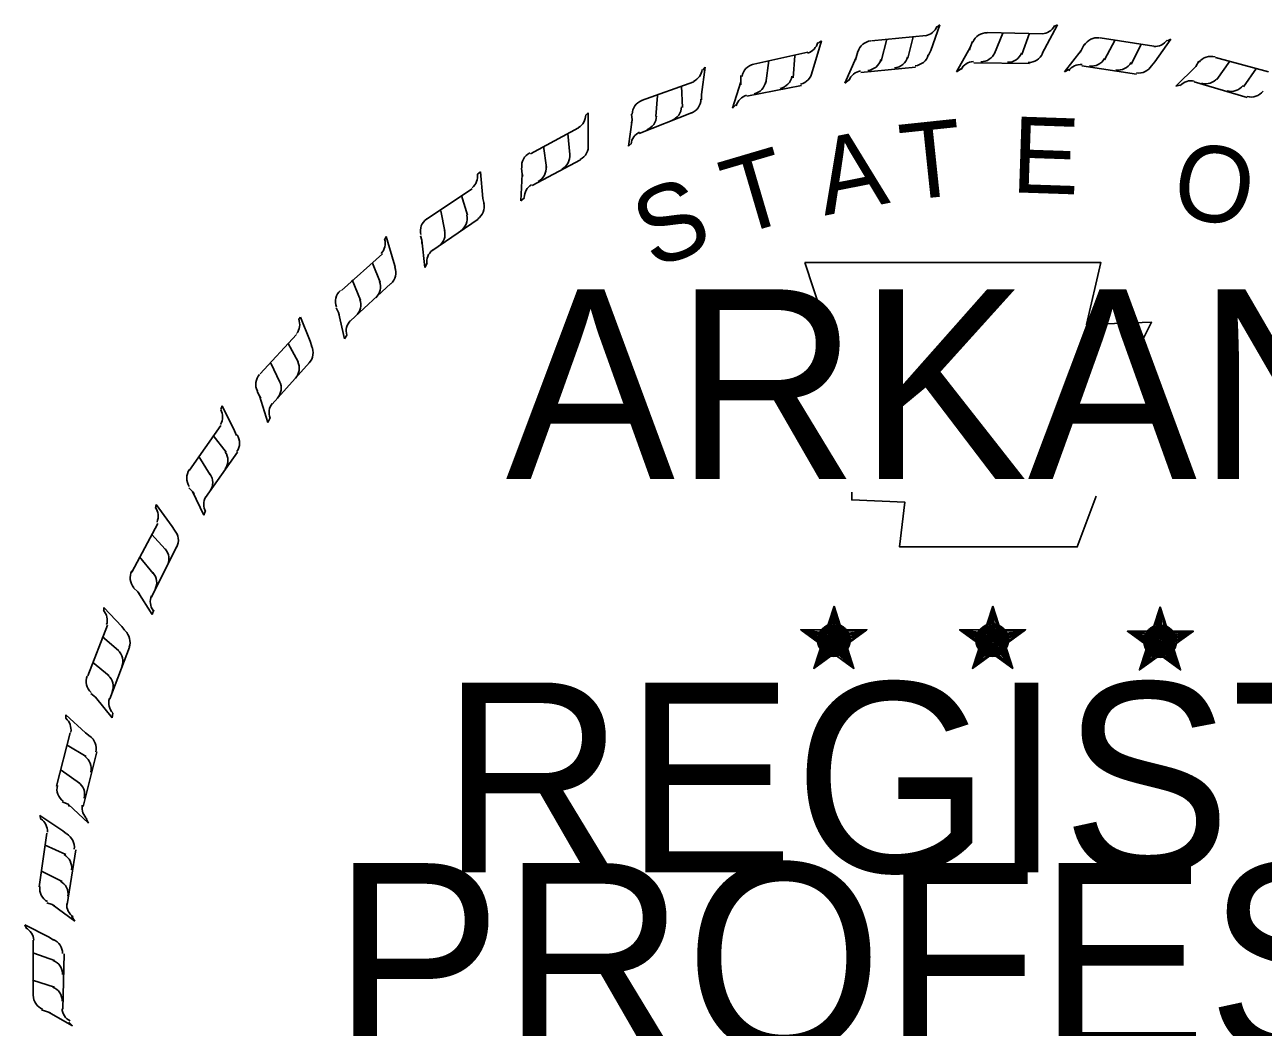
# Model space of a CAD drawing. Extents: x 117751.5 to 117785.6, y 28052.1 to 28074.
# Drawn here: x 117776.184 to 117777.407, y 28054.465 to 28055.456 of the extents above; entities that cross this region are included whole.
import ezdxf

# ---------------------------------------------------------------- set-up
doc = ezdxf.new("R2010")
doc.units = 0
doc.layers.add('Stamp-ChrisC', color=7, linetype='Continuous')

msp = doc.modelspace()

# ---------------------------------------------------------------- linework, layer by layer
at = {"layer": 'Stamp-ChrisC'}
for p, q in [((117777.0784, 28055.4301), (117777.0874, 28055.4556)), ((117777.0874, 28055.4556), (117777.0844, 28055.4533)), ((117777.1909, 28055.4316), (117777.2036, 28055.4556)), ((117777.2036, 28055.4556), (117777.2006, 28055.4541)), ((117776.9629, 28055.4143), (117776.9704, 28055.4398)), ((117776.9704, 28055.4398), (117776.9674, 28055.4376)), ((117777.0199, 28055.4398), (117777.0739, 28055.4451)), ((117777.0296, 28055.4196), (117777.0349, 28055.4413)), ((117777.0559, 28055.4226), (117777.0611, 28055.4436)), ((117777.1196, 28055.4391), (117777.1174, 28055.4331)), ((117777.1346, 28055.4481), (117777.1886, 28055.4466)), ((117777.1414, 28055.4271), (117777.1496, 28055.4473)), ((117777.1684, 28055.4263), (117777.1759, 28055.4473)), ((117777.2456, 28055.4428), (117777.2989, 28055.4346)), ((117777.2501, 28055.4211), (117777.2606, 28055.4406)), ((117777.2996, 28055.4188), (117777.3154, 28055.4413)), ((117777.3154, 28055.4413), (117777.3124, 28055.4398)), ((117776.9036, 28055.4166), (117776.9569, 28055.4286)), ((117777.0064, 28055.4293), (117777.0049, 28055.4233)), ((117777.0761, 28055.4256), (117777.0784, 28055.4301)), ((117777.1174, 28055.4331), (117777.1039, 28055.4091)), ((117777.1174, 28055.4331), (117777.1166, 28055.4308)), ((117777.1886, 28055.4271), (117777.1909, 28055.4316)), ((117777.2269, 28055.4301), (117777.2104, 28055.4091)), ((117777.2269, 28055.4301), (117777.2261, 28055.4286)), ((117777.2299, 28055.4361), (117777.2269, 28055.4301)), ((117777.2764, 28055.4166), (117777.2861, 28055.4361)), ((117776.8519, 28055.3866), (117776.8556, 28055.4136)), ((117776.8556, 28055.4136), (117776.8534, 28055.4106)), ((117776.9156, 28055.3978), (117776.9186, 28055.4203)), ((117776.9426, 28055.4031), (117776.9441, 28055.4248)), ((117776.9614, 28055.4091), (117776.9629, 28055.4143)), ((117777.0049, 28055.4233), (117776.9936, 28055.3978)), ((117777.0049, 28055.4233), (117777.0041, 28055.4211)), ((117777.0634, 28055.4136), (117777.0094, 28055.4083)), ((117777.1759, 28055.4173), (117777.1211, 28055.4181)), ((117777.2816, 28055.4068), (117777.2276, 28055.4151)), ((117777.2966, 28055.4151), (117777.2996, 28055.4188)), ((117777.3401, 28055.4143), (117777.3206, 28055.3948)), ((117777.3401, 28055.4143), (117777.3386, 28055.4128)), ((117777.3431, 28055.4196), (117777.3401, 28055.4143)), ((117777.3596, 28055.4233), (117777.4121, 28055.4091)), ((117777.3611, 28055.4016), (117777.3739, 28055.4196)), ((117776.8909, 28055.4053), (117776.8909, 28055.3993)), ((117776.9936, 28055.3978), (117776.9981, 28055.4016)), ((117777.1039, 28055.4091), (117777.1084, 28055.4121)), ((117777.2104, 28055.4091), (117777.2149, 28055.4113)), ((117777.3874, 28055.3941), (117777.4001, 28055.4128)), ((117776.7926, 28055.3806), (117776.8444, 28055.3993)), ((117776.8331, 28055.3738), (117776.8324, 28055.3948)), ((117776.8909, 28055.3993), (117776.8826, 28055.3731)), ((117776.8909, 28055.3993), (117776.8909, 28055.3963)), ((117776.9509, 28055.3956), (117776.8969, 28055.3851)), ((117777.3206, 28055.3948), (117777.3259, 28055.3963)), ((117777.3911, 28055.3836), (117777.3386, 28055.3993)), ((117776.8069, 28055.3648), (117776.8084, 28055.3858)), ((117776.8519, 28055.3813), (117776.8519, 28055.3866)), ((117776.8826, 28055.3731), (117776.8864, 28055.3768)), ((117776.7401, 28055.3686), (117776.7379, 28055.3663)), ((117776.7401, 28055.3423), (117776.7401, 28055.3686)), ((117776.7829, 28055.3671), (117776.7836, 28055.3618)), ((117776.8421, 28055.3686), (117776.7904, 28055.3483)), ((117776.6831, 28055.3281), (117776.7304, 28055.3536)), ((117776.7836, 28055.3618), (117776.7799, 28055.3356)), ((117776.7836, 28055.3618), (117776.7829, 28055.3588)), ((117776.7221, 28055.3273), (117776.7199, 28055.3483)), ((117776.7401, 28055.3371), (117776.7401, 28055.3423)), ((117776.6989, 28055.3146), (117776.6959, 28055.3356)), ((117776.7799, 28055.3356), (117776.7829, 28055.3386)), ((117776.7326, 28055.3221), (117776.6846, 28055.2966)), ((117776.6336, 28055.3101), (117776.6306, 28055.3078)), ((117776.6359, 28055.2838), (117776.6336, 28055.3101)), ((117776.6749, 28055.3078), (117776.6734, 28055.2816)), ((117776.6741, 28055.3138), (117776.6749, 28055.3078)), ((117776.6749, 28055.3078), (117776.6756, 28055.3056)), ((117776.5804, 28055.2636), (117776.6254, 28055.2936)), ((117776.6209, 28055.2673), (117776.6149, 28055.2868)), ((117776.6374, 28055.2786), (117776.6359, 28055.2838)), ((117776.6734, 28055.2816), (117776.6771, 28055.2846)), ((117776.5984, 28055.2516), (117776.5946, 28055.2718)), ((117776.6314, 28055.2636), (117776.5856, 28055.2321)), ((117776.5406, 28055.2463), (117776.5391, 28055.2433)), ((117776.5481, 28055.2208), (117776.5406, 28055.2463)), ((117776.5744, 28055.2471), (117776.5759, 28055.2426)), ((117776.5759, 28055.2426), (117776.5789, 28055.2156)), ((117776.5759, 28055.2426), (117776.5759, 28055.2396)), ((117776.4964, 28055.1931), (117776.5369, 28055.2291)), ((117776.5346, 28055.2013), (117776.5271, 28055.2201)), ((117776.5496, 28055.2163), (117776.5481, 28055.2208)), ((117776.5789, 28055.2156), (117776.5811, 28055.2201)), ((117776.5451, 28055.1998), (117776.5054, 28055.1631)), ((117776.5151, 28055.1833), (117776.5069, 28055.2036)), ((117776.4911, 28055.1758), (117776.4934, 28055.1713)), ((117776.4934, 28055.1713), (117776.4994, 28055.1451)), ((117776.4934, 28055.1713), (117776.4941, 28055.1691)), ((117776.4559, 28055.1668), (117776.4544, 28055.1646)), ((117776.4656, 28055.1428), (117776.4559, 28055.1668)), ((117776.4161, 28055.1106), (117776.4521, 28055.1496)), ((117776.4994, 28055.1451), (117776.5016, 28055.1488)), ((117776.4536, 28055.1226), (117776.4439, 28055.1406)), ((117776.4671, 28055.1376), (117776.4656, 28055.1428)), ((117776.4356, 28055.1023), (117776.4266, 28055.1211)), ((117776.4649, 28055.1218), (117776.4281, 28055.0806)), ((117776.4131, 28055.0933), (117776.4154, 28055.0888)), ((117776.4154, 28055.0888), (117776.4236, 28055.0626)), ((117776.4154, 28055.0888), (117776.4169, 28055.0866)), ((117776.3786, 28055.0791), (117776.3771, 28055.0753)), ((117776.3906, 28055.0543), (117776.3786, 28055.0791)), ((117776.3464, 28055.0153), (117776.3771, 28055.0596)), ((117776.4236, 28055.0626), (117776.4259, 28055.0671)), ((117776.3824, 28055.0333), (117776.3696, 28055.0498)), ((117776.3929, 28055.0498), (117776.3906, 28055.0543)), ((117776.3666, 28055.0108), (117776.3554, 28055.0288)), ((117776.3936, 28055.0333), (117776.3621, 28054.9883)), ((117776.3456, 28054.9981), (117776.3494, 28054.9943)), ((117776.3494, 28054.9943), (117776.3606, 28054.9711)), ((117776.3494, 28054.9943), (117776.3509, 28054.9921)), ((117776.3134, 28054.9816), (117776.3126, 28054.9778)), ((117776.3291, 28054.9598), (117776.3134, 28054.9816)), ((117776.3606, 28054.9711), (117776.3621, 28054.9756)), ((117776.2894, 28054.9148), (117776.3149, 28054.9628)), ((117776.3224, 28054.9373), (117776.3089, 28054.9523)), ((117776.3314, 28054.9561), (117776.3291, 28054.9598)), ((117776.3336, 28054.9396), (117776.3089, 28054.8901)), ((117776.3104, 28054.9133), (117776.2969, 28054.9298)), ((117776.2909, 28054.8991), (117776.2954, 28054.8953)), ((117776.2954, 28054.8953), (117776.3096, 28054.8728)), ((117776.2954, 28054.8953), (117776.2969, 28054.8931)), ((117776.2796, 28054.8608), (117776.2616, 28054.8796)), ((117776.2616, 28054.8796), (117776.2616, 28054.8766)), ((117776.3096, 28054.8728), (117776.3111, 28054.8773)), ((117776.9831, 28054.8811), (117776.9779, 28054.8586)), ((117776.9831, 28054.8811), (117776.9794, 28054.8578)), ((117776.9831, 28054.8811), (117776.9816, 28054.8578)), ((117776.9831, 28054.8473), (117776.9831, 28054.8811)), ((117776.9831, 28054.8811), (117776.9891, 28054.8578)), ((117776.9831, 28054.8811), (117776.9876, 28054.8578)), ((117776.9831, 28054.8811), (117776.9854, 28054.8578)), ((117777.1399, 28054.8811), (117777.1339, 28054.8586)), ((117777.1399, 28054.8811), (117777.1361, 28054.8578)), ((117777.1399, 28054.8811), (117777.1376, 28054.8578)), ((117777.1399, 28054.8473), (117777.1399, 28054.8811)), ((117777.1399, 28054.8811), (117777.1459, 28054.8578)), ((117777.1399, 28054.8811), (117777.1444, 28054.8578)), ((117777.1399, 28054.8811), (117777.1414, 28054.8578)), ((117777.3049, 28054.8803), (117777.2996, 28054.8571)), ((117777.3049, 28054.8803), (117777.3011, 28054.8571)), ((117777.3049, 28054.8803), (117777.3034, 28054.8571)), ((117777.3049, 28054.8458), (117777.3049, 28054.8803)), ((117777.3049, 28054.8803), (117777.3116, 28054.8571)), ((117777.3049, 28054.8803), (117777.3101, 28054.8571)), ((117777.3049, 28054.8803), (117777.3071, 28054.8571)), ((117776.2459, 28054.8121), (117776.2654, 28054.8623)), ((117776.2766, 28054.8368), (117776.2601, 28054.8511)), ((117776.2826, 28054.8571), (117776.2796, 28054.8608)), ((117776.9501, 28054.8578), (117776.9831, 28054.8473)), ((117776.9501, 28054.8578), (117776.9741, 28054.8548)), ((117776.9501, 28054.8578), (117776.9741, 28054.8533)), ((117776.9501, 28054.8578), (117776.9734, 28054.8518)), ((117776.9501, 28054.8578), (117776.9726, 28054.8481)), ((117776.9501, 28054.8578), (117776.9726, 28054.8458)), ((117776.9501, 28054.8578), (117776.9726, 28054.8436)), ((117777.0154, 28054.8578), (117776.9831, 28054.8473)), ((117777.0154, 28054.8578), (117776.9869, 28054.8556)), ((117777.0154, 28054.8578), (117776.9891, 28054.8526)), ((117777.0154, 28054.8578), (117776.9891, 28054.8511)), ((117777.0154, 28054.8578), (117776.9951, 28054.8488)), ((117777.0154, 28054.8578), (117776.9966, 28054.8481)), ((117777.0154, 28054.8578), (117776.9981, 28054.8466)), ((117777.1069, 28054.8578), (117777.1399, 28054.8473)), ((117777.1069, 28054.8578), (117777.1309, 28054.8548)), ((117777.1069, 28054.8578), (117777.1301, 28054.8533)), ((117777.1069, 28054.8578), (117777.1301, 28054.8518)), ((117777.1069, 28054.8578), (117777.1294, 28054.8481)), ((117777.1069, 28054.8578), (117777.1286, 28054.8458)), ((117777.1069, 28054.8578), (117777.1286, 28054.8436)), ((117777.1721, 28054.8578), (117777.1399, 28054.8473)), ((117777.1721, 28054.8578), (117777.1436, 28054.8556)), ((117777.1721, 28054.8578), (117777.1451, 28054.8526)), ((117777.1721, 28054.8578), (117777.1451, 28054.8511)), ((117777.1721, 28054.8578), (117777.1511, 28054.8488)), ((117777.1721, 28054.8578), (117777.1526, 28054.8481)), ((117777.1721, 28054.8578), (117777.1541, 28054.8466)), ((117777.2726, 28054.8563), (117777.3049, 28054.8458)), ((117777.2726, 28054.8563), (117777.2966, 28054.8541)), ((117777.2726, 28054.8563), (117777.2966, 28054.8526)), ((117777.2726, 28054.8563), (117777.2951, 28054.8503)), ((117777.2726, 28054.8563), (117777.2951, 28054.8473)), ((117777.2726, 28054.8563), (117777.2944, 28054.8451)), ((117777.2726, 28054.8563), (117777.2944, 28054.8428)), ((117777.3379, 28054.8563), (117777.3049, 28054.8458)), ((117777.3379, 28054.8563), (117777.3086, 28054.8541)), ((117777.3379, 28054.8563), (117777.3109, 28054.8518)), ((117777.3379, 28054.8563), (117777.3109, 28054.8503)), ((117777.3379, 28054.8563), (117777.3169, 28054.8481)), ((117777.3379, 28054.8563), (117777.3184, 28054.8466)), ((117777.3379, 28054.8563), (117777.3199, 28054.8458)), ((117776.2871, 28054.8406), (117776.2676, 28054.7896)), ((117776.9629, 28054.8196), (117776.9831, 28054.8473)), ((117776.9629, 28054.8196), (117776.9734, 28054.8451)), ((117776.9629, 28054.8196), (117776.9749, 28054.8421)), ((117776.9629, 28054.8196), (117776.9764, 28054.8413)), ((117776.9629, 28054.8196), (117776.9831, 28054.8398)), ((117776.9629, 28054.8196), (117776.9794, 28054.8391)), ((117777.0026, 28054.8196), (117776.9831, 28054.8473)), ((117777.0026, 28054.8196), (117776.9831, 28054.8391)), ((117777.0026, 28054.8196), (117776.9861, 28054.8391)), ((117777.0026, 28054.8196), (117776.9891, 28054.8421)), ((117777.0026, 28054.8196), (117776.9899, 28054.8466)), ((117777.0026, 28054.8196), (117776.9921, 28054.8466)), ((117777.1196, 28054.8196), (117777.1399, 28054.8473)), ((117777.1196, 28054.8196), (117777.1301, 28054.8451)), ((117777.1196, 28054.8196), (117777.1309, 28054.8421)), ((117777.1196, 28054.8196), (117777.1331, 28054.8413)), ((117777.1196, 28054.8196), (117777.1391, 28054.8398)), ((117777.1196, 28054.8196), (117777.1361, 28054.8391)), ((117777.1594, 28054.8196), (117777.1391, 28054.8391)), ((117777.1594, 28054.8196), (117777.1399, 28054.8473)), ((117777.1594, 28054.8196), (117777.1429, 28054.8391)), ((117777.1594, 28054.8196), (117777.1459, 28054.8421)), ((117777.1594, 28054.8196), (117777.1466, 28054.8466)), ((117777.1594, 28054.8196), (117777.1489, 28054.8466)), ((117777.2846, 28054.8181), (117777.3049, 28054.8458)), ((117777.2846, 28054.8181), (117777.2951, 28054.8436)), ((117777.2846, 28054.8181), (117777.2966, 28054.8413)), ((117777.2846, 28054.8181), (117777.2989, 28054.8406)), ((117777.2846, 28054.8181), (117777.3049, 28054.8383)), ((117777.3251, 28054.8181), (117777.3049, 28054.8458)), ((117777.3251, 28054.8181), (117777.3049, 28054.8383)), ((117777.3251, 28054.8181), (117777.3116, 28054.8413)), ((117777.3251, 28054.8181), (117777.3124, 28054.8451)), ((117777.3251, 28054.8181), (117777.3146, 28054.8458)), ((117776.9629, 28054.8196), (117776.9831, 28054.8368)), ((117777.0026, 28054.8196), (117776.9831, 28054.8368)), ((117777.1196, 28054.8196), (117777.1399, 28054.8368)), ((117777.1594, 28054.8196), (117777.1391, 28054.8368)), ((117777.2846, 28054.8181), (117777.3011, 28054.8376)), ((117777.2846, 28054.8181), (117777.3056, 28054.8361)), ((117777.3251, 28054.8181), (117777.3049, 28054.8353)), ((117777.3251, 28054.8181), (117777.3086, 28054.8376)), ((117776.2669, 28054.8121), (117776.2504, 28054.8256)), ((117776.2489, 28054.7948), (117776.2534, 28054.7911)), ((117776.2534, 28054.7911), (117776.2699, 28054.7708)), ((117776.2534, 28054.7911), (117776.2549, 28054.7896)), ((117776.2436, 28054.7558), (117776.2241, 28054.7738)), ((117776.2241, 28054.7738), (117776.2241, 28054.7701)), ((117776.2699, 28054.7708), (117776.2706, 28054.7753)), ((117776.2151, 28054.7033), (117776.2286, 28054.7558)), ((117776.2481, 28054.7521), (117776.2436, 28054.7558)), ((117776.2444, 28054.7326), (117776.2256, 28054.7438)), ((117776.2549, 28054.7371), (117776.2414, 28054.6831)), ((117776.2376, 28054.7063), (117776.2196, 28054.7191)), ((117776.2204, 28054.6876), (117776.2264, 28054.6853)), ((117776.2264, 28054.6853), (117776.2466, 28054.6666)), ((117776.2264, 28054.6853), (117776.2279, 28054.6831)), ((117776.2211, 28054.6591), (117776.1986, 28054.6741)), ((117776.1986, 28054.6741), (117776.1994, 28054.6703)), ((117776.2466, 28054.6666), (117776.2444, 28054.6711)), ((117776.1979, 28054.6036), (117776.2054, 28054.6568)), ((117776.2249, 28054.6561), (117776.2211, 28054.6591)), ((117776.2241, 28054.6358), (117776.2039, 28054.6448)), ((117776.2339, 28054.6403), (117776.2256, 28054.5863)), ((117776.2204, 28054.6088), (117776.2001, 28054.6193)), ((117776.2054, 28054.5878), (117776.2106, 28054.5863)), ((117776.2106, 28054.5863), (117776.2331, 28054.5698)), ((117776.2106, 28054.5863), (117776.2129, 28054.5848)), ((117776.2331, 28054.5698), (117776.2301, 28054.5743)), ((117776.2076, 28054.5541), (117776.1836, 28054.5661)), ((117776.1836, 28054.5661), (117776.1851, 28054.5631)), ((117776.1919, 28054.4971), (117776.1919, 28054.5511)), ((117776.2121, 28054.5511), (117776.2076, 28054.5541)), ((117776.2129, 28054.5308), (117776.1926, 28054.5383)), ((117776.2226, 28054.5376), (117776.2211, 28054.4828)), ((117776.2129, 28054.5046), (117776.1911, 28054.5113)), ((117776.2001, 28054.4821), (117776.2069, 28054.4798)), ((117776.2069, 28054.4798), (117776.2309, 28054.4663)), ((117776.2069, 28054.4798), (117776.2091, 28054.4791)), ((117776.2309, 28054.4663), (117776.2271, 28054.4701))]:
    msp.add_line(p, q, dxfattribs=at)
for points in [[(117776.9539, 28055.2208), (117776.9794, 28055.1436)], [(117777.2831, 28055.1346), (117777.2966, 28055.1616), (117777.2321, 28055.1593), (117777.2464, 28055.2208), (117776.9539, 28055.2208)], [(117777.0004, 28054.9936), (117777.0004, 28054.9861), (117777.0529, 28054.9838), (117777.0476, 28054.9396), (117777.2231, 28054.9396), (117777.2419, 28054.9898)], [(117776.9831, 28054.8811), (117777.0026, 28054.8196), (117776.9501, 28054.8578), (117777.0154, 28054.8578), (117776.9629, 28054.8196), (117776.9831, 28054.8811)], [(117777.1399, 28054.8811), (117777.1594, 28054.8196), (117777.1069, 28054.8578), (117777.1721, 28054.8578), (117777.1196, 28054.8196), (117777.1399, 28054.8811)], [(117777.3049, 28054.8803), (117777.3251, 28054.8181), (117777.2726, 28054.8563), (117777.3379, 28054.8563), (117777.2846, 28054.8181), (117777.3049, 28054.8803)]]:
    msp.add_lwpolyline(points, dxfattribs=at)
for centre, radius in [((117776.9828, 28054.8474), 0.0161), ((117777.1392, 28054.8474), 0.0161), ((117777.3049, 28054.8463), 0.0161), ((117776.9828, 28054.8474), 0.0146), ((117776.9828, 28054.8474), 0.0136), ((117776.9828, 28054.8474), 0.0124), ((117776.9828, 28054.8474), 0.0109), ((117776.9828, 28054.8474), 0.0101), ((117776.9828, 28054.8474), 0.00929), ((117776.9828, 28054.8474), 0.008), ((117776.9828, 28054.8474), 0.00701), ((117776.9828, 28054.8474), 0.00583), ((117776.9828, 28054.8474), 0.00464), ((117776.9828, 28054.8474), 0.00346), ((117776.9828, 28054.8474), 0.00278), ((117777.1392, 28054.8474), 0.0146), ((117777.1392, 28054.8474), 0.0136), ((117777.1392, 28054.8474), 0.0124), ((117777.1392, 28054.8474), 0.0109), ((117777.1392, 28054.8474), 0.0101), ((117777.1392, 28054.8474), 0.00929), ((117777.1392, 28054.8474), 0.008), ((117777.1392, 28054.8474), 0.00701), ((117777.1392, 28054.8474), 0.00583), ((117777.1392, 28054.8474), 0.00464), ((117777.1392, 28054.8474), 0.00346), ((117777.1392, 28054.8474), 0.00278), ((117777.3049, 28054.8463), 0.0146), ((117777.3049, 28054.8463), 0.0136), ((117777.3049, 28054.8463), 0.0124), ((117777.3049, 28054.8463), 0.0109), ((117777.3049, 28054.8463), 0.0101), ((117777.3049, 28054.8463), 0.00929), ((117777.3049, 28054.8463), 0.008), ((117777.3049, 28054.8463), 0.00701), ((117777.3049, 28054.8463), 0.00583), ((117777.3049, 28054.8463), 0.00464), ((117776.9828, 28054.8474), 0.00135), ((117777.1392, 28054.8474), 0.00135), ((117777.3049, 28054.8463), 0.00346), ((117777.3049, 28054.8463), 0.00278), ((117777.3049, 28054.8463), 0.00135)]:
    msp.add_circle(centre, radius, dxfattribs=at)
for centre, start, end in [((117777.0708, 28055.4593), 279.9249, 338.7128), ((117777.1875, 28055.4614), 273.4236, 332.2115), ((117776.9526, 28055.4419), 286.2701, 345.0579), ((117777.0207, 28055.4249), 95.6641, 164.0381), ((117777.1338, 28055.4328), 89.1628, 157.5368), ((117777.2428, 28055.4279), 81.4231, 149.797), ((117777.2998, 28055.449), 265.6839, 324.4717), ((117777.0617, 28055.4298), 275.6641, 344.0381), ((117777.1281, 28055.4338), 269.1628, 337.5368), ((117777.1545, 28055.4333), 269.1628, 337.5368), ((117777.175, 28055.433), 269.1628, 337.5368), ((117776.9066, 28055.4021), 102.0093, 170.3833), ((117777.0149, 28055.4252), 275.6641, 344.0381), ((117777.0413, 28055.4277), 275.6641, 344.0381), ((117777.1214, 28055.4045), 93.4236, 152.2115), ((117777.2267, 28055.4016), 85.6839, 144.4717), ((117777.2373, 28055.4296), 261.4231, 329.797), ((117777.2634, 28055.4256), 261.4231, 329.797), ((117777.2837, 28055.4226), 261.4231, 329.797), ((117777.3551, 28055.4096), 73.9909, 142.3649), ((117776.8379, 28055.4131), 294.8371, 353.6249), ((117776.9267, 28055.4072), 282.0093, 350.3833), ((117776.9467, 28055.4115), 282.0093, 350.3833), ((117777.0116, 28055.3954), 99.9249, 158.7128), ((117777.3498, 28055.412), 253.9909, 322.3649), ((117776.9008, 28055.4018), 282.0093, 350.3833), ((117777.3357, 28055.3855), 78.2517, 137.0395), ((117777.3752, 28055.4046), 253.9909, 322.3649), ((117777.395, 28055.399), 253.9909, 322.3649), ((117776.7983, 28055.3669), 110.5763, 178.9503), ((117776.8366, 28055.3822), 290.5763, 358.9503), ((117776.9007, 28055.3718), 106.2701, 165.0579), ((117776.7228, 28055.3665), 301.9545, 0.7423), ((117776.7927, 28055.3657), 290.5763, 358.9503), ((117776.8174, 28055.3749), 290.5763, 358.9503), ((117776.7971, 28055.3361), 114.8371, 173.6249), ((117776.6892, 28055.3158), 117.6937, 186.0677), ((117776.7072, 28055.3261), 297.6937, 6.0677), ((117776.7254, 28055.3357), 297.6937, 6.0677), ((117776.6838, 28055.3139), 297.6937, 6.0677), ((117776.6161, 28055.306), 309.1135, 7.9014), ((117776.6918, 28055.285), 121.9545, 180.7423), ((117776.6225, 28055.2758), 304.8528, 13.2267), ((117776.6057, 28055.264), 304.8528, 13.2267), ((117776.5891, 28055.2516), 124.8528, 193.2267), ((117776.5248, 28055.2397), 316.8235, 15.6113), ((117776.5839, 28055.249), 304.8528, 13.2267), ((117776.5955, 28055.2213), 129.1135, 187.9014), ((117776.5353, 28055.2106), 312.5627, 20.9367), ((117776.5054, 28055.1821), 132.5627, 200.9367), ((117776.5202, 28055.1967), 312.5627, 20.9367), ((117776.5007, 28055.1789), 312.5627, 20.9367), ((117776.4404, 28055.1594), 322.2653, 21.0531), ((117776.5159, 28055.153), 136.8235, 195.6113), ((117776.4536, 28055.1314), 318.0045, 26.3785), ((117776.4399, 28055.1161), 318.0045, 26.3785), ((117776.4266, 28055.1002), 138.0045, 206.3785), ((117776.4221, 28055.0966), 318.0045, 26.3785), ((117776.3642, 28055.0681), 329.9636, 28.7515), ((117776.4397, 28055.0723), 142.2653, 201.0531), ((117776.381, 28055.0421), 325.7028, 34.0768), ((117776.3694, 28055.0251), 325.7028, 34.0768), ((117776.3584, 28055.0076), 145.7028, 214.0768), ((117776.3545, 28055.0033), 325.7028, 34.0768), ((117776.3752, 28054.9816), 149.9636, 208.7515), ((117776.3006, 28054.9699), 337.2243, 36.0121), ((117776.3205, 28054.9463), 332.9635, 41.3375), ((117776.3112, 28054.9279), 332.9635, 41.3375), ((117776.3025, 28054.9091), 152.9635, 221.3375), ((117776.2991, 28054.9044), 332.9635, 41.3375), ((117776.3224, 28054.8855), 157.2243, 216.0121), ((117776.2503, 28054.867), 343.6465, 42.4343), ((117776.2728, 28054.8457), 339.3857, 47.7597), ((117776.2656, 28054.8265), 339.3857, 47.7597), ((117776.259, 28054.8068), 159.3857, 227.7597), ((117776.2562, 28054.8017), 339.3857, 47.7597), ((117776.2814, 28054.7855), 163.6465, 222.4343), ((117776.2145, 28054.759), 350.445, 49.2329), ((117776.2393, 28054.7405), 346.1842, 54.5582), ((117776.2344, 28054.7206), 346.1842, 54.5582), ((117776.2302, 28054.7003), 166.1842, 234.5582), ((117776.228, 28054.6949), 346.1842, 54.5582), ((117776.255, 28054.6818), 170.445, 229.2329), ((117776.1912, 28054.6587), 356.646, 55.4338), ((117776.2178, 28054.643), 352.3852, 60.7592), ((117776.2152, 28054.6226), 352.3852, 60.7592), ((117776.2116, 28054.5964), 352.3852, 60.7592), ((117776.2132, 28054.602), 172.3852, 240.7592), ((117776.2398, 28054.5863), 176.646, 235.4338), ((117776.1778, 28054.5499), 3.9474, 62.7352), ((117776.2062, 28054.5378), 359.6866, 68.0606), ((117776.2062, 28054.5172), 359.6866, 68.0606), ((117776.2068, 28054.4965), 179.6866, 248.0606), ((117776.2059, 28054.4908), 359.6866, 68.0606), ((117776.2352, 28054.4843), 183.9474, 242.7352)]:
    msp.add_arc(centre, 0.0148, start, end, dxfattribs=at)

# ---------------------------------------------------------------- texts
for s, rotation, p in [('E', 358.0732, (117777.1574, 28055.2901)), ('T', 6.0228, (117777.0524, 28055.2819)), ('A', 11.2132, (117776.9736, 28055.2669)), ('T', 16.4036, (117776.8866, 28055.2466)), ('O', 350.4515, (117777.3141, 28055.2676)), ('S', 21.594, (117776.8041, 28055.2136))]:
    msp.add_text(s, height=0.075, rotation=rotation, dxfattribs=at).set_placement(p)
for s, height, p in [('ARKANSAS', 0.1875, (117776.6586, 28055.0066)), ('REGISTERED', 0.1875, (117776.5949, 28054.6181)), ('PROFESSIONAL', 0.187497, (117776.4876, 28054.4396))]:
    msp.add_text(s, height=height, dxfattribs=at).set_placement(p)

doc.saveas('drawing.dxf')
